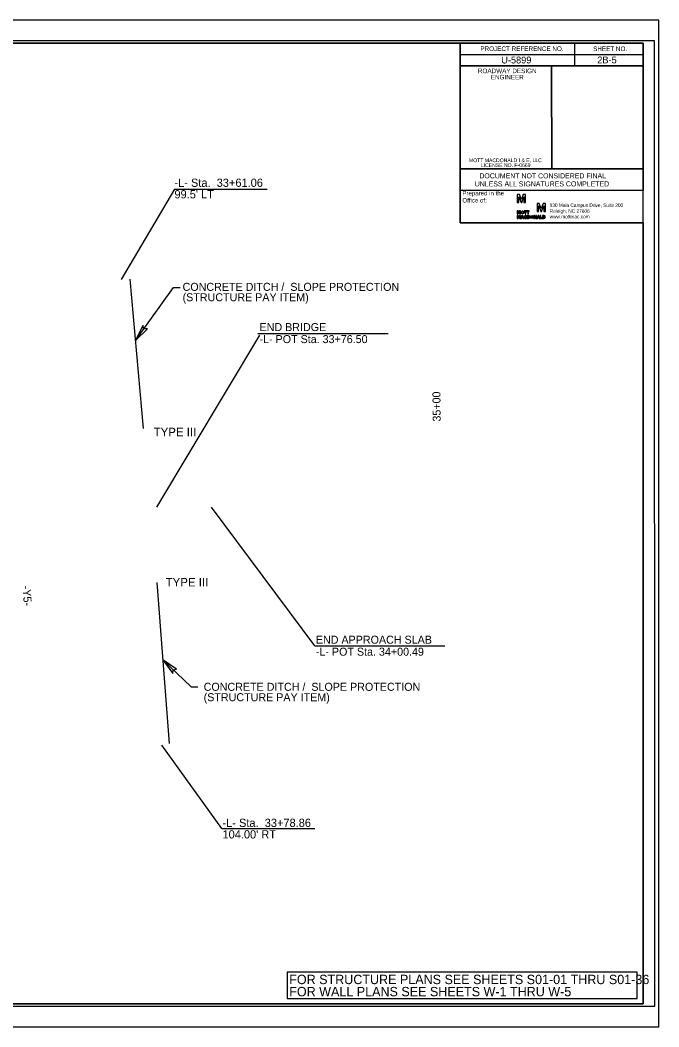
# Model space of a CAD drawing. Extents: x 1619649 to 1620848, y 897814 to 898268.
# Drawn here: x 1620043.9 to 1620323, y 897814.1 to 898254.1 of the extents above; entities that cross this region are included whole.
import ezdxf

# ---------------------------------------------------------------- set-up
doc = ezdxf.new("R2010")
doc.units = 0
for name, color, linetype in [('Old_Level_2', 7, 'Continuous'), ('Old_Level_40', 7, 'Continuous'), ('Old_Level_42', 7, 'Continuous'), ('Old_Level_45', 7, 'Continuous'), ('Prop DSN Text', 7, 'Continuous'), ('Prop Earthen Structure Ditch Flow Line', 7, 'Continuous'), ('Prop Guardrail Anchor Unit CELL', 7, 'Continuous'), ('Prop Horizontal Alignment Direction Label', 7, 'Continuous'), ('Prop Horizontal Alignment Tick Label', 7, 'Continuous'), ('Prop Terminator CELL', 7, 'Continuous'), ('Scratch_Level_7', 7, 'Continuous'), ('Sheet Cutting Line CELL', 7, 'Continuous'), ('Sheet Data Field CELL', 7, 'Continuous'), ('Sheet Layout Plan Border', 7, 'Continuous'), ('Sheet Plan CELL', 7, 'Continuous'), ('Sheet Plot Border Inside CELL', 7, 'Continuous'), ('Sheet Plot Border Outside CELL', 7, 'Continuous'), ('Sheet Sticker Exception Certification CELL', 7, 'Continuous'), ('Sheet Typical CELL', 7, 'Continuous')]:
    doc.layers.add(name, color=color, linetype=linetype)

msp = doc.modelspace()

# ---------------------------------------------------------------- linework, layer by layer
at = {"layer": 'Old_Level_2'}
for p, q in [((1620262.11, 898177.88), (1620261.1, 898177.88)), ((1620261.1, 898177.88), (1620261.1, 898174.48)), ((1620261.82, 898174.48), (1620261.82, 898176.92)), ((1620261.82, 898176.92), (1620261.83, 898176.92)), ((1620261.83, 898176.92), (1620262.79, 898174.48)), ((1620262.93, 898175.78), (1620262.11, 898177.88)), ((1620262.93, 898175.75), (1620262.93, 898175.78)), ((1620262.95, 898175.75), (1620262.93, 898175.75)), ((1620263.77, 898177.88), (1620262.95, 898175.78)), ((1620262.95, 898175.78), (1620262.95, 898175.75)), ((1620263.1, 898174.48), (1620264.05, 898176.93)), ((1620264.78, 898177.88), (1620263.77, 898177.88)), ((1620264.05, 898176.93), (1620264.07, 898176.93)), ((1620264.07, 898176.93), (1620264.06, 898174.48)), ((1620264.78, 898174.48), (1620264.78, 898177.88)), ((1620261.1, 898174.48), (1620261.82, 898174.48)), ((1620262.79, 898174.48), (1620263.1, 898174.48)), ((1620264.06, 898174.48), (1620264.78, 898174.48)), ((1620270.76, 898173.92), (1620269.75, 898173.92)), ((1620269.75, 898173.92), (1620269.75, 898170.52)), ((1620270.47, 898170.52), (1620270.47, 898172.96)), ((1620270.47, 898172.96), (1620270.48, 898172.96)), ((1620270.48, 898172.96), (1620271.43, 898170.52)), ((1620271.58, 898171.82), (1620270.76, 898173.92)), ((1620271.58, 898171.78), (1620271.58, 898171.82)), ((1620271.6, 898171.78), (1620271.58, 898171.78)), ((1620272.42, 898173.92), (1620271.6, 898171.82)), ((1620271.6, 898171.82), (1620271.6, 898171.78)), ((1620271.74, 898170.52), (1620272.7, 898172.97)), ((1620273.43, 898173.92), (1620272.42, 898173.92)), ((1620272.7, 898172.97), (1620272.71, 898172.97)), ((1620272.71, 898172.97), (1620272.71, 898170.52)), ((1620273.43, 898170.52), (1620273.43, 898173.92)), ((1620261.49, 898170.75), (1620261.1, 898170.75)), ((1620261.1, 898170.75), (1620261.1, 898169.45)), ((1620261.1, 898169.45), (1620261.37, 898169.45)), ((1620261.49, 898168.74), (1620261.1, 898168.74)), ((1620261.1, 898168.74), (1620261.1, 898167.44)), ((1620261.1, 898167.44), (1620261.37, 898167.44)), ((1620261.37, 898169.45), (1620261.37, 898170.39)), ((1620261.37, 898170.39), (1620261.38, 898170.39)), ((1620261.37, 898170.39), (1620261.38, 898170.39)), ((1620261.37, 898167.44), (1620261.37, 898168.37)), ((1620261.37, 898168.37), (1620261.38, 898168.37)), ((1620261.38, 898170.39), (1620261.75, 898169.45)), ((1620261.38, 898168.37), (1620261.75, 898167.44)), ((1620261.81, 898169.94), (1620261.49, 898170.75)), ((1620261.81, 898167.93), (1620261.49, 898168.74)), ((1620261.75, 898169.45), (1620261.87, 898169.45)), ((1620261.75, 898167.44), (1620261.87, 898167.44)), ((1620262.13, 898170.75), (1620261.81, 898169.94)), ((1620262.13, 898168.74), (1620261.81, 898167.93)), ((1620261.87, 898169.45), (1620262.24, 898170.39)), ((1620261.87, 898167.44), (1620262.24, 898168.37)), ((1620262.52, 898170.75), (1620262.13, 898170.75)), ((1620262.52, 898168.74), (1620262.13, 898168.74)), ((1620262.24, 898170.39), (1620262.25, 898170.39)), ((1620262.24, 898170.39), (1620262.25, 898170.39)), ((1620262.24, 898170.39), (1620262.25, 898170.39)), ((1620262.24, 898168.37), (1620262.25, 898168.37)), ((1620262.25, 898170.39), (1620262.25, 898169.45)), ((1620262.25, 898169.45), (1620262.52, 898169.45)), ((1620262.25, 898168.37), (1620262.25, 898167.44)), ((1620262.25, 898167.44), (1620262.52, 898167.44)), ((1620262.52, 898169.45), (1620262.52, 898170.75)), ((1620262.52, 898167.44), (1620262.52, 898168.74)), ((1620265.25, 898167.71), (1620265.02, 898167.82)), ((1620265.25, 898167.71), (1620265.02, 898167.81)), ((1620265.05, 898168.31), (1620265.28, 898168.42)), ((1620265.05, 898168.31), (1620265.28, 898168.42)), ((1620266.05, 898168.74), (1620265.46, 898168.74)), ((1620265.46, 898168.74), (1620265.46, 898168.06)), ((1620265.46, 898168.06), (1620265.46, 898167.44)), ((1620265.46, 898167.44), (1620266.05, 898167.44)), ((1620265.73, 898167.69), (1620265.73, 898168.5)), ((1620265.73, 898168.5), (1620266.05, 898168.5)), ((1620266.05, 898167.69), (1620265.73, 898167.69)), ((1620269.75, 898170.52), (1620270.47, 898170.52)), ((1620271.43, 898170.52), (1620271.74, 898170.52)), ((1620272.19, 898168.74), (1620272.19, 898168.74)), ((1620272.78, 898168.74), (1620272.19, 898168.74)), ((1620272.19, 898168.74), (1620272.19, 898168.06)), ((1620272.19, 898168.06), (1620272.19, 898167.44)), ((1620272.19, 898167.44), (1620272.78, 898167.44)), ((1620272.46, 898167.69), (1620272.46, 898168.5)), ((1620272.46, 898168.5), (1620272.78, 898168.5)), ((1620272.78, 898167.69), (1620272.46, 898167.69)), ((1620272.71, 898170.52), (1620273.43, 898170.52)), ((1620272.78, 898168.49), (1620272.78, 898168.49))]:
    msp.add_line(p, q, dxfattribs=at)
for points in [[(1620262.67, 898167.44), (1620262.98, 898167.44), (1620263.07, 898167.66), (1620263.63, 898167.66), (1620263.71, 898167.44), (1620264.01, 898167.44), (1620263.51, 898168.74), (1620263.17, 898168.74), (1620262.67, 898167.44)], [(1620263.14, 898167.9), (1620263.35, 898168.46), (1620263.56, 898167.9), (1620263.14, 898167.9)], [(1620264.15, 898170.52), (1620264.52, 898170.52), (1620264.52, 898169.46), (1620264.8, 898169.46), (1620264.8, 898170.52), (1620265.18, 898170.52), (1620265.18, 898170.75), (1620264.15, 898170.75), (1620264.15, 898170.52)], [(1620265.34, 898170.52), (1620265.72, 898170.52), (1620265.72, 898169.46), (1620266, 898169.46), (1620266, 898170.52), (1620266.37, 898170.52), (1620266.37, 898170.75), (1620265.34, 898170.75), (1620265.34, 898170.52)], [(1620268.64, 898168.28), (1620268.65, 898168.28), (1620269.28, 898167.44), (1620269.53, 898167.44), (1620269.53, 898168.74), (1620269.26, 898168.74), (1620269.26, 898167.92), (1620268.65, 898168.74), (1620268.38, 898168.74), (1620268.38, 898167.44), (1620268.64, 898167.44), (1620268.64, 898168.28)], [(1620269.7, 898167.44), (1620270.01, 898167.44), (1620270.1, 898167.66), (1620270.66, 898167.66), (1620270.74, 898167.44), (1620271.04, 898167.44), (1620270.54, 898168.74), (1620270.2, 898168.74), (1620269.7, 898167.44)], [(1620270.17, 898167.9), (1620270.38, 898168.46), (1620270.58, 898167.9), (1620270.17, 898167.9)], [(1620272.03, 898167.44), (1620272.03, 898167.67), (1620271.47, 898167.67), (1620271.47, 898168.74), (1620271.2, 898168.74), (1620271.2, 898167.44), (1620272.03, 898167.44)]]:
    msp.add_lwpolyline(points, dxfattribs=at)
msp.add_arc((1620272.78, 898168.09), 0.65, 270.0047, 90.0047, dxfattribs=at)
for centre, major_axis, ratio in [((1620263.4, 898170.1), (0, 0.65), 0.993118), ((1620263.4, 898170.1), (0, 0.423), 0.916103), ((1620267.51, 898168.09), (0, 0.65), 0.993118), ((1620267.51, 898168.09), (0, 0.423), 0.916103)]:
    msp.add_ellipse(centre, major_axis=major_axis, ratio=ratio, dxfattribs=at)
for centre, major_axis, ratio, start_param, end_param in [((1620264.73, 898168.09), (0, 0.65), 0.993118, 5.246647, 10.366427), ((1620264.73, 898168.09), (0, 0.423), 0.916103, 5.276876, 10.296021), ((1620266.05, 898168.09), (0, -0.649), 0.930276, 0, 3.141593), ((1620266.05, 898168.09), (0, -0.405), 0.900832, 0, 3.141593), ((1620272.78, 898168.09), (0, -0.405), 0.900832, 0, 3.141593)]:
    msp.add_ellipse(centre, major_axis=major_axis, ratio=ratio, start_param=start_param, end_param=end_param, dxfattribs=at)
at = {"layer": 'Old_Level_40'}
msp.add_lwpolyline([(1620313.53, 897837.96), (1620160.6, 897837.96), (1620160.6, 897826.49), (1620313.53, 897826.49)], close=True, dxfattribs=at)
at = {"layer": 'Old_Level_42'}
msp.add_lwpolyline([(1620316.16, 898165.6), (1620236.14, 898165.6), (1620236.14, 898179.72)], dxfattribs=at)
at = {"layer": 'Prop DSN Text'}
for p, q in [((1620111.39, 898180.3), (1620088.05, 898140.74)), ((1620111.39, 898180.3), (1620151.79, 898180.3)), ((1620094.34, 898114.13), (1620110.95, 898137.27)), ((1620110.95, 898137.27), (1620113.85, 898137.27)), ((1620148.51, 898116.47), (1620103.49, 898041.24)), ((1620147.84, 898117.23), (1620204.71, 898117.23)), ((1620172.67, 897980.57), (1620127.48, 898041.24)), ((1620172.67, 897980.57), (1620229.45, 897980.57)), ((1620106.2, 897974.49), (1620118.67, 897962.66)), ((1620118.67, 897962.66), (1620121.57, 897962.66)), ((1620132.09, 897900.76), (1620105.85, 897937.24)), ((1620132.09, 897900.76), (1620172.7, 897900.76))]:
    msp.add_line(p, q, dxfattribs=at)
at = {"layer": 'Prop Earthen Structure Ditch Flow Line'}
for p, q in [((1620097.78, 898075.69), (1620091.94, 898140.87)), ((1620103.59, 898008.3), (1620109, 897938.02))]:
    msp.add_line(p, q, dxfattribs=at)
at = {"layer": 'Prop Terminator CELL'}
for points in [[(1620097.53, 898120.7), (1620094.34, 898114.13), (1620099.6, 898119.27), (1620098.02, 898119.26)], [(1620112.28, 897970.43), (1620106.2, 897974.49), (1620110.57, 897968.58), (1620110.78, 897970.14)]]:
    msp.add_lwpolyline(points, close=True, dxfattribs=at)
at = {"layer": 'Scratch_Level_7'}
msp.add_lwpolyline([(1619716.14, 898178.12), (1619881.16, 898178.13), (1619881.15, 898244.11), (1620236.13, 898244.14), (1620236.14, 898165.6), (1620316.16, 898165.6), (1620316.19, 897824.14), (1619716.17, 897824.09)], close=True, dxfattribs=at)
at = {"layer": 'Sheet Cutting Line CELL'}
for p, q in [((1620322.95, 898254.14), (1619649.35, 898254.09)), ((1619649.39, 897814.09), (1620322.99, 897814.14))]:
    msp.add_line(p, q, dxfattribs=at)
at = {"layer": 'Sheet Layout Plan Border'}
msp.add_lwpolyline([(1619716.17, 897824.09), (1620316.18, 897824.14), (1620316.15, 898165.6), (1620236.14, 898165.6), (1620236.13, 898244.14), (1619716.14, 898244.1)], close=True, dxfattribs=at)
at = {"layer": 'Sheet Plan CELL'}
for p, q in [((1620286.13, 898244.11), (1620286.15, 898234.11)), ((1620236.12, 898239.12), (1620316.14, 898239.12)), ((1620236.12, 898234.11), (1620316.14, 898234.12)), ((1620236.12, 898234.11), (1620316.14, 898234.12)), ((1620236.12, 898234.11), (1620236.12, 898229.11))]:
    msp.add_line(p, q, dxfattribs=at)
msp.add_lwpolyline([(1620236.12, 898244.14), (1620316.15, 898244.14), (1620316.14, 898234.12), (1620236.12, 898234.11)], close=True, dxfattribs=at)
at = {"layer": 'Sheet Plot Border Inside CELL'}
msp.add_lwpolyline([(1620321.15, 898245.16), (1619654.55, 898245.11), (1619654.59, 897823.07), (1620321.19, 897823.12)], close=True, dxfattribs=at)
at = {"layer": 'Sheet Plot Border Outside CELL'}
msp.add_lwpolyline([(1620322.95, 898254.14), (1619649.35, 898254.09), (1619649.39, 897814.09), (1620322.99, 897814.14)], close=True, dxfattribs=at)
at = {"layer": 'Sheet Sticker Exception Certification CELL'}
for p, q in [((1620236.14, 898179.72), (1620236.14, 898189.12)), ((1620236.14, 898189.12), (1620316.15, 898189.12)), ((1620316.15, 898189.12), (1620316.15, 898179.72)), ((1620316.15, 898179.72), (1620236.14, 898179.72))]:
    msp.add_line(p, q, dxfattribs=at)
at = {"layer": 'Sheet Typical CELL'}
for p, q in [((1620286.15, 898244.12), (1620286.15, 898234.12)), ((1620236.13, 898239.12), (1620316.15, 898239.12)), ((1620276.15, 898234.12), (1620276.16, 898189.14))]:
    msp.add_line(p, q, dxfattribs=at)
for points in [[(1620316.15, 898244.14), (1619716.15, 898244.09), (1619716.19, 897824.09), (1620316.19, 897824.14)], [(1620236.13, 898244.14), (1620316.15, 898244.14), (1620316.15, 898234.12), (1620236.13, 898234.12)], [(1620236.13, 898234.12), (1620276.15, 898234.12), (1620276.16, 898189.12), (1620236.14, 898189.12)], [(1620276.15, 898234.12), (1620316.15, 898234.12), (1620316.16, 898189.12), (1620276.16, 898189.12)]]:
    msp.add_lwpolyline(points, close=True, dxfattribs=at)

# ---------------------------------------------------------------- texts
at = {"layer": 'Old_Level_2'}
for s, height, p in [('Office of:', 1.927, (1620237.16, 898174.42)), ('Prepared in the ', 1.9274, (1620237.16, 898177.52)), ('930 Main Campus Drive, Suite 200', 1.5, (1620275.27, 898172.51)), ('Raleigh, NC 27606', 1.5, (1620275.27, 898169.93)), ('www.mottmac.com', 1.5, (1620275.27, 898167.49))]:
    msp.add_text(s, height=height, rotation=0.0047, dxfattribs=at).set_placement(p)
at = {"layer": 'Old_Level_45'}
for s, p in [('MOTT MACDONALD I & E, LLC', (1620240.02, 898192.06)), (' LICENSE NO. F-0669', (1620244.58, 898189.92))]:
    msp.add_text(s, height=1.6071, rotation=0.0047, dxfattribs=at).set_placement(p)
at = {"layer": 'Prop DSN Text'}
for s, height, rotation, p in [('-L- Sta.  33+61.06', 3.6, 0.0047, (1620111.33, 898181.26)), ("99.5' LT", 3.6, 0.0047, (1620111.33, 898176.22)), ('END BRIDGE', 3.5, 360, (1620148.51, 898118.22)), ('-L- POT Sta. 33+76.50', 3.5, 360, (1620148.51, 898112.97)), ('END APPROACH SLAB', 3.5, 360, (1620173.12, 897981.57)), ('-L- POT Sta. 34+00.49', 3.5, 360, (1620173.12, 897976.32)), ('-L- Sta.  33+78.86', 3.6, 0.0047, (1620132.32, 897901.47)), ("104.00' RT", 3.6, 0.0047, (1620132.32, 897896.43))]:
    msp.add_text(s, height=height, rotation=rotation, dxfattribs=at).set_placement(p)
for s, height, p in [('CONCRETE DITCH /  SLOPE PROTECTION', 3.5, (1620114.89, 898135.81)), ('(STRUCTURE PAY ITEM)', 3.5, (1620114.89, 898131.26)), ('CONCRETE DITCH /  SLOPE PROTECTION', 3.5, (1620124.09, 897960.98)), ('(STRUCTURE PAY ITEM)', 3.5, (1620124.09, 897956.43)), ('FOR STRUCTURE PLANS SEE SHEETS S01-01 THRU S01-36', 4.095, (1620161.49, 897832.77)), ('FOR WALL PLANS SEE SHEETS W-1 THRU W-5', 4.095, (1620161.49, 897827.45))]:
    msp.add_text(s, height=height, dxfattribs=at).set_placement(p)
at = {"layer": 'Prop Guardrail Anchor Unit CELL'}
for p in [(1620102.22, 898072.22), (1620107.46, 898006.58)]:
    msp.add_text('TYPE III', height=3.75, rotation=0, dxfattribs=at).set_placement(p)
at = {"layer": 'Prop Horizontal Alignment Direction Label'}
msp.add_text('-Y5-', height=3.5, rotation=274.2279, dxfattribs=at).set_placement((1620044.91, 898006.74))
at = {"layer": 'Prop Horizontal Alignment Tick Label'}
msp.add_text('35+00', height=3.5, rotation=90.7102, dxfattribs=at).set_placement((1620227.69, 898078.68))
at = {"layer": 'Sheet Data Field CELL'}
for s, p in [('U-5899', (1620254.13, 898235.21)), ('2B-5', (1620296.08, 898235.24))]:
    msp.add_text(s, height=3, rotation=0.0047, dxfattribs=at).set_placement(p)
at = {"layer": 'Sheet Plan CELL'}
for s, p in [('PROJECT REFERENCE NO.', (1620245, 898240.65)), ('SHEET NO.', (1620294.27, 898240.61))]:
    msp.add_text(s, height=2, rotation=0.0047, dxfattribs=at).set_placement(p)
at = {"layer": 'Sheet Sticker Exception Certification CELL'}
for s, p in [('DOCUMENT NOT CONSIDERED FINAL', (1620244.57, 898184.98)), ('UNLESS ALL SIGNATURES COMPLETED', (1620242.54, 898181.46))]:
    msp.add_text(s, height=2.2, rotation=0.0047, dxfattribs=at).set_placement(p)
at = {"layer": 'Sheet Typical CELL'}
for s, p in [('PROJECT REFERENCE NO.', (1620245.01, 898240.66)), ('SHEET NO.', (1620294.27, 898240.62)), ('ROADWAY DESIGN', (1620243.93, 898230.96)), ('ENGINEER', (1620249.55, 898228.22))]:
    msp.add_text(s, height=2, rotation=0.0047, dxfattribs=at).set_placement(p)

doc.saveas('drawing.dxf')
